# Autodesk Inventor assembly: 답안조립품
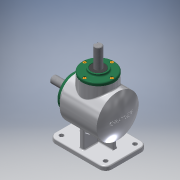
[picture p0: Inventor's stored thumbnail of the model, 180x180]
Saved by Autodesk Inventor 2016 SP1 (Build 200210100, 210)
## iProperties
Created: 2016-09
Part Number: 답안조립품
Document SubType Name: Assembly
Designer: Administrator
Author: Administrator
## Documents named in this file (14)
- D:\460907V1006\답안조립품.iam
- C:\Users\Administrator\Desktop\460907V1006\본체1.ipt
- D:\460907V1006\베어링 6203.ipt
- D:\460907V1006\메인 축.ipt
- 메인 축.ipt
- D:\460907V1006\키 5x5.ipt
- D:\460907V1006\커버.ipt
- D:\460907V1006\오일실 17 32 8.ipt
- D:\460907V1006\M4.ipt
- D:\460907V1006\메인 베벨기어.ipt
- D:\460907V1006\서브 베벨기어.ipt
- D:\460907V1006\키 4x4.ipt
- D:\460907V1006\서브 축.ipt
- 서브 축.ipt
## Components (8 placed, 1 different names)
1. M4:1
2. M4:2
3. M4:3
4. M4:4
5. M4:5
6. M4:6
7. M4:7
8. M4:8
